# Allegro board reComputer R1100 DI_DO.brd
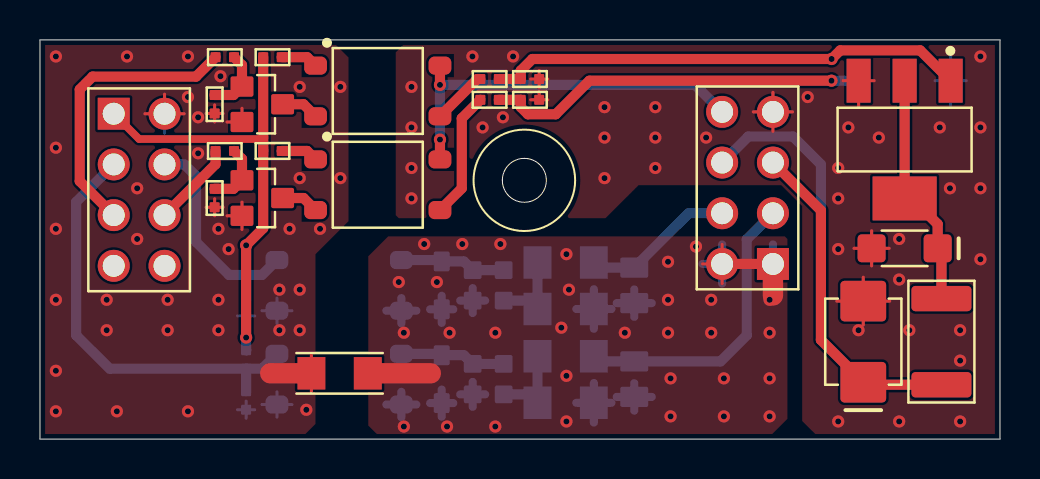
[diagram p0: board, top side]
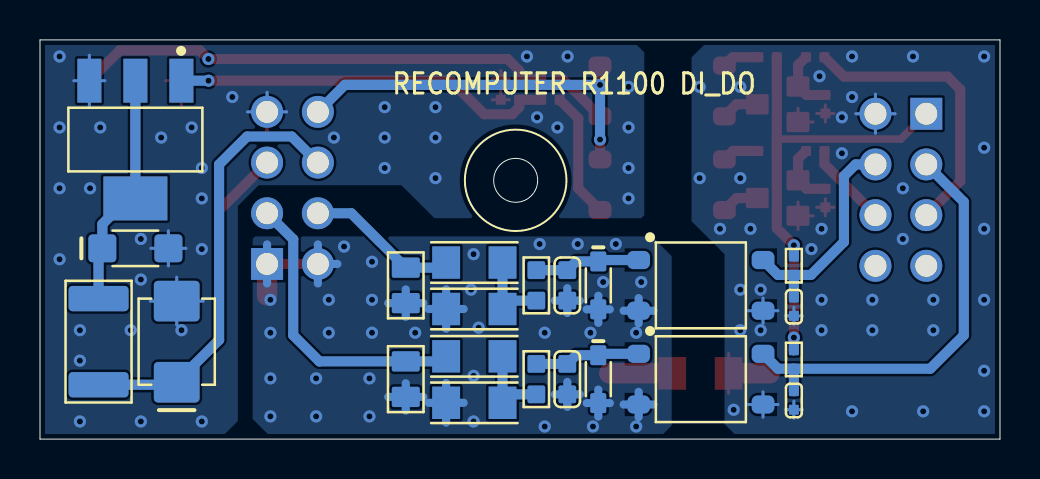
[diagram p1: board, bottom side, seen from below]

Outline 48 x 20 mm; copper layers: TOP, BOTTOM. Coordinates in mm from the lower left corner of the outline.
Outline path: circle c24.22,12.97 r1.1 ; 0,20 0,0 48,0 48,20 0,20

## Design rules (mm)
constraint set DEFAULT: min track width 0.152

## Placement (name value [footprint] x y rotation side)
C1  100nF  [C0603]  21.63 7.7 270 bottom
C2  10pF  [C0402]  10.31 6.63 270 bottom
C3  100nF  [C0603]  21.63 3 270 bottom
C4  10pF  [C0402]  10.31 1.94 270 bottom
D1  B5819WS SL  [SOD_323]  20.09 7.7 90 bottom
D2  B5819WS SL  [SOD_323]  20.09 3 90 bottom
D3  LMSZ5266BT1G  [SOD_123]  43.23 9.56 180 bottom
D4  SMBJ60CA/TR13  [DO_214AA_SMB]  41.16 4.88 270 bottom
D5  LMSZ5266BT1G  [SOD_123]  43.23 9.56 180 top
D6  SMBJ60CA/TR13  [DO_214AA_SMB]  41.16 4.88 270 top
F1  0.5A  [F1812]  45.07 4.88 270 bottom
F2  0.5A  [F1812]  45.07 4.88 270 top
J1  ST-PH-0096-2X4P-H2.0-PA3.0  [HEADER2X4P_2D54_DIP]  4.96 12.49 0 top
J2  ST-PH-0096-2X4P-H2.0-PA3.0  [HEADER2X4P_2D54_DIP]  35.38 12.58 180 top
Q1  SFH690BT3  [SOP4-2_54MM]  14.96 7.7 270 bottom
Q2  SFH690BT3  [SOP4-2_54MM]  14.96 3 270 bottom
Q3  SFH690BT3  [SOP4-2_54MM]  16.89 12.74 270 top
Q4  BCP56  [SOT223_4]  43.23 15.01 270 bottom
Q5  BSS138  [SOT23]  11.12 12.08 180 top
Q6  SFH690BT3  [SOP4-2_54MM]  16.89 17.44 270 top
Q7  BCP56  [SOT223_4]  43.23 15.01 270 top
Q8  BSS138  [SOT23]  11.12 16.78 180 top
R1  1M  [R1206]  14.98 3.3 180 top
R2  10K  [R0402]  10.31 8.69 270 bottom
R3  10K  [R0402]  10.31 3.99 270 bottom
R4  2.2K  [R1206]  26.28 8.85 180 bottom
R5  0R  [R0603]  23.18 7.7 90 bottom
R6  2.2K  [R1206]  26.28 4.15 180 bottom
R7  0R  [R0603]  23.18 3 90 bottom
R8  SDV2012A300C181NPTF  [R0805]  29.71 7.7 270 bottom
R9  2.2K  [R1206]  26.28 6.52 0 bottom
R10  2.2K  [R1206]  26.28 1.82 0 bottom
R11  SDV2012A300C181NPTF  [R0805]  29.71 3 270 bottom
R12  120R  [R0402]  11.62 14.44 0 top
R13  330R  [R0402]  22.48 17 0 top
R14  10K  [R0402]  24.5 17 0 top
R15  0R  [R0402]  9.24 14.44 0 top
R16  10K  [R0402]  8.73 12.08 270 top
R17  120R  [R0402]  11.62 19.14 0 top
R18  330R  [R0402]  22.48 18.04 0 top
R19  10K  [R0402]  24.5 18.04 0 top
R20  0R  [R0402]  9.24 19.14 0 top
R21  10K  [R0402]  8.73 16.78 270 top

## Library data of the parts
C1-C4 = CC
D1 D2 = D
D3 D5 = DIODE TVS
D4 D6 = DIODE TVS BI-DIR
F1 F2 = Fuse
J1 J2 = Header 2X4
Q1-Q3 Q6 = Optoisolator_4P
Q4 Q7 = NPN_4P
Q5 Q8 = NMOS_123
R1-R7 R9 R10 R12-R21 = R
R8 R11 = VDR

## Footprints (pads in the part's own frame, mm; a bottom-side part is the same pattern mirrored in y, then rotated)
C0402
  rrect 0.5x0.5 smd: 1(-0.463,0) 2(0.463,0)
C0603
  rrect 0.889x0.889 smd: 1(-0.762,0) 2(0.762,0)
DO_214AA_SMB
  rrect 2.032x2.286 smd: 1(-2.032,0) 2(2.032,0)
F1812
  rrect 1.27x3 smd: 1(-2.159,0) 2(2.159,0)
HEADER2X4P_2D54_DIP
  rect 1.6x1.6 hole 1.1: 1(-1.27,3.81)
  round 1.6 hole 1.1: 2(1.27,3.81) 3(-1.27,1.27) 4(1.27,1.27) 5(-1.27,-1.27) 6(1.27,-1.27) 7(-1.27,-3.81) 8(1.27,-3.81)
R0402
  rrect 0.5x0.5 smd: 1(-0.463,0) 2(0.463,0)
R0603
  rrect 0.889x0.889 smd: 1(-0.762,0) 2(0.762,0)
R0805
  rrect 1.016x1.397 smd: 1(-0.889,0) 2(0.889,0)
R1206
  rect 1.397x1.626 smd: 1(-1.41,0) 2(1.41,0)
SOD_123
  rrect 1.397x1.397 smd: 1(1.651,0) 2(-1.651,0)
SOD_323
  rrect 1x0.8 smd: 1(-1.2,0) 2(1.2,0)
SOP4-2_54MM
  rrect 0.91x1.14 smd: 1(-1.27,-3.11) 2(1.27,-3.11) 3(1.27,3.11) 4(-1.27,3.11)
SOT23
  rrect 1.143x1.016 smd: 1(1.016,-0.889) 2(1.016,0.889) 3(-1.016,0)
SOT223_4
  rect 2.2x1.2 smd: 1(-2.95,2.3) 2(-2.95,0) 3(-2.95,-2.3)
  rect 2.2x3.2 smd: 4(2.95,0)

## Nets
GND: C2.2 C4.2 J1.2 Q1.3(EMITTER) Q2.3(EMITTER) Q5.2(S) Q8.2(S) R1.2 R16.2 R21.2
GND_DO: D3.1 D4.1 D5.1 D6.1 J2.7 Q4.3(EMITTER) Q7.3(EMITTER) R14.2 R19.2
GND_ISO_DI: C1.2 C3.2 D1.1 D2.1 J2.1 J2.2 Q1.2 Q2.2 R1.1 R8.2 R9.2 R10.2 R11.2
VDD_3.3V: J1.1 R2.1 R3.1 R12.1 R17.1
CM4_IN1: C2.1 J1.4 Q1.4 R2.2
CM4_IN2: C4.1 J1.3 Q2.4 R3.2
CM4_OUTPUT1: J1.6 R15.1
CM4_OUTPUT2: J1.5 R20.1
DO_VDD: J2.8 Q3.4 Q6.4
EXT_IN1: J2.4 R4.1 R8.1
EXT_IN2: J2.3 R6.1 R11.1
EXT_OUT1: D4.2 F1.2 J2.6
EXT_OUT2: D6.2 F2.2 J2.5
N12939: R4.2 R5.1 R9.1
N12951: C1.1 D1.2(C) Q1.1 R5.2
N12997: R6.2 R7.1 R10.1
N13009: C3.1 D2.2(C) Q2.1 R7.2
N14695: D3.2(C) F1.1 Q4.2 Q4.4
N14789: Q3.1 R12.2
N14847: Q3.2 Q5.3
N14855: Q3.3(EMITTER) R13.1
N14859: Q4.1 R13.2 R14.1
N15023: Q5.1 R15.2 R16.1
N15163: D5.2(C) F2.1 Q7.2 Q7.4
N15257: Q6.1 R17.2
N15315: Q6.2 Q8.3
N15323: Q6.3(EMITTER) R18.1
N15327: Q7.1 R18.2 R19.1
N15491: Q8.1 R20.2 R21.1

Pads without a net: J1 7 8

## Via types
v1: diameter 0.61, hole 0.305, TOP to BOTTOM, 108 vias

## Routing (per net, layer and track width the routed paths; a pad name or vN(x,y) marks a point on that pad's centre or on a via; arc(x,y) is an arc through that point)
GND: length 26.8
  TOP w0.152: 8.3,11.62 R16.2 ; R16.2 8.73,12.04 ; R16.2 9.16,11.62 ; R16.2 8.73,11.19 ; 10.1,10.5 Q5.2 ; Q5.2 9.35,11.19 ; Q5.2 10.1,11.88 ; 8.73,15.89 R21.2 ; R21.2 8.3,16.31 ; R21.2 8.73,16.74 ; R21.2 9.16,16.31 ; J1.2 6.23,17.28 ; J1.2 7.21,16.3 ; J1.2 5.25,16.3 ; 9.35,15.89 Q8.2 10.1,16.57 ; 13.57,4.29 R1.2 13.57,2.31
  TOP w1.016: R1.2 11.51,3.3
  BOTTOM w0.152: C2.2 10.31,6.6 ; C2.2 10.74,6.17 ; C2.2 10.31,5.74 ; C2.2 9.88,6.17 ; Q1.3 12.6,6.43 ; Q1.3 11.85,7.07 ; Q1.3 11.1,6.43 ; Q1.3 11.85,5.8 ; C4.2 10.74,1.47 ; C4.2 9.88,1.47 ; C4.2 10.31,1.9 ; C4.2 10.31,1.04 ; J1.2 7.21,16.3 ; J1.2 6.23,15.32 ; J1.2 5.25,16.3 ; J1.2 6.23,17.28 ; Q2.3 11.85,2.37 ; Q2.3 11.1,1.73 ; Q2.3 12.6,1.73 ; Q2.3 11.85,1.1
  vias: v1(0.79,19.17) v1(0.79,14.6) v1(0.79,10.54) v1(0.79,6.98) v1(0.79,3.42) v1(0.79,1.39) v1(3.33,6.98) v1(3.33,5.46) v1(3.84,1.39) v1(4.35,19.17) v1(4.86,12.57) v1(4.86,10.03) v1(6.38,6.98) v1(6.38,5.46) v1(7.4,19.17) v1(7.4,17.14) v1(7.4,1.39) v1(7.91,16.12) v1(7.91,14.32) v1(8.92,10.54) v1(8.92,6.98) v1(8.92,5.46) v1(9.02,18.18) v1(9.43,9.52) v1(11.97,7.49) v1(11.97,5.46) v1(12.48,10.54) v1(12.99,17.65) v1(12.99,13.08) v1(12.99,7.49) v1(12.99,5.46) v1(13.32,1.47) v1(14,10.54) v1(15.02,17.65) v1(15.02,13.08)
GND_DO: length 33.9
  TOP w0.152: D6.1 42.49,6.91 ; D6.1 39.84,6.91 ; D6.1 41.16,8.11 ; D6.1 41.16,5.72 ; Q7.3 41.71,17.96 ; Q7.3 40.93,16.68 ; Q7.3 40.15,17.96 ; R14.2 25.39,17 ; R14.2 24.96,17.43 ; R14.2 24.53,17 ; D5.1 41.58,10.43 ; D5.1 42.46,9.56 ; D5.1 40.7,9.56 ; D5.1 41.58,8.68 ; J2.7 37.63,16.39 ; J2.7 36.65,15.42 ; J2.7 36.65,17.37 ; J2.7 35.67,16.39 ; 24.96,17.61 R19.2 ; R19.2 24.53,18.04 ; R19.2 24.96,18.47 ; R19.2 25.39,18.04
  BOTTOM w0.152: D6.1 41.16,8.11 ; D6.1 41.16,5.72 ; D6.1 42.49,6.91 ; D6.1 39.84,6.91 ; 40.7,9.56 D5.1 ; D5.1 42.46,9.56 ; D5.1 41.58,10.43 ; D5.1 41.58,8.68 ; Q4.3 45.53,19.24 ; Q4.3 45.53,16.68 ; Q4.3 46.31,17.96 ; Q4.3 44.75,17.96 ; J2.7 36.65,17.37 ; J2.7 37.63,16.39 ; J2.7 35.67,16.39
  vias: v1(18.57,17.65) v1(18.57,15.62) v1(18.57,13.58) v1(18.57,12.06) v1(21.62,19.17) v1(22.13,15.62) v1(23.15,16.12) v1(23.65,19.17) v1(28.23,16.63) v1(28.23,15.11) v1(28.23,13.08) v1(30.77,16.63) v1(30.77,15.11) v1(30.77,13.58) v1(33.31,15.11) v1(38.39,17.14) v1(39.91,13.58) v1(39.91,12.06) v1(39.91,9.52) v1(39.91,0.88) v1(40.42,15.62) v1(40.93,5.46) v1(41.94,15.11) v1(42.96,10.03) v1(42.96,8) v1(42.96,0.88) v1(43.47,5.46) v1(44.99,15.62) v1(45.5,12.57) v1(46.01,5.46) v1(46.01,3.93) v1(46.01,0.88) v1(47.02,19.17) v1(47.02,15.62) v1(47.02,12.57) v1(47.02,9.01)
GND_ISO_DI: length 44.4
  TOP w0.152: 33.13,8.77 J2.2 ; J2.2 34.11,7.8 ; J2.2 34.11,9.75
  TOP w0.508: J2.1 J2.2
  TOP w1.016: J2.1 36.65,7.19 ; R1.1 19.54,3.3
  BOTTOM w0.406: 26.82,6.52 R9.2 ; R9.2 28.57,6.52 ; R9.2 27.69,7.51 ; R9.2 27.69,5.53 ; 28.84,6.81 R8.2 ; R8.2 29.71,6.13 ; R8.2 29.71,7.5 ; R8.2 30.59,6.81 ; 33.13,8.77 J2.2 ; J2.2 34.11,9.75 ; J2.2 34.11,7.8 ; D1.1 20.66,6.5 ; D1.1 19.51,6.5 ; D1.1 20.09,7.18 ; D1.1 20.09,5.82 ; D2.1 20.66,1.8 ; D2.1 20.09,1.12 ; D2.1 19.51,1.8 ; D2.1 20.09,2.48 ; 27.69,0.83 R10.2 ; R10.2 28.57,1.82 ; R10.2 27.69,2.81 ; R10.2 26.82,1.82 ; 28.84,2.11 R11.2 ; R11.2 29.71,1.43 ; R11.2 30.59,2.11 ; R11.2 29.71,2.8 ; 36.65,9.75 J2.1 36.65,7.8 ; C1.2 21.63,7.56 ; C1.2 22.26,6.94 ; C1.2 21.01,6.94 ; C1.2 21.63,6.32 ; Q1.2 18.07,7.07 ; Q1.2 18.82,6.43 ; Q1.2 18.07,5.8 ; Q1.2 17.32,6.43 ; Q2.2 18.82,1.73 ; Q2.2 17.32,1.73 ; Q2.2 18.07,2.37 ; Q2.2 18.07,1.1 ; C3.2 22.26,2.24 ; C3.2 21.01,2.24 ; C3.2 21.63,1.62 ; C3.2 21.63,2.86
  vias: v1(17.94,7.87) v1(18.19,5.33) v1(18.19,0.63) v1(19.21,9.77) v1(19.84,7.87) v1(20.35,0.63) v1(20.48,5.33) v1(21.11,9.77) v1(22.77,5.33) v1(22.77,0.63) v1(23.02,9.77) v1(26.07,5.58) v1(26.32,9.27) v1(26.32,3.17) v1(26.32,0.88) v1(26.45,7.49) v1(29.24,5.33) v1(31.4,8.88) v1(31.4,6.98) v1(31.4,5.33) v1(31.53,3.04) v1(31.53,1.14) v1(32.8,9.65) v1(33.56,6.98) v1(33.56,5.33) v1(34.2,3.04) v1(34.2,1.14) v1(36.48,6.98) v1(36.48,5.33) v1(36.48,3.04) v1(36.48,1.14)
VDD_3.3V: length 23.6
  TOP w0.381: 11.16,15.11 11.09,15.03 4.96,15.03 J1.1
  TOP w0.508: v1(10.31,5.09) v1(10.31,9.71) 11.16,10.56 R12.1 R17.1
  BOTTOM w0.508: 10.31,4.45 R3.1 v1(10.31,5.09) ; R2.1 v1(10.31,9.71)
CM4_IN1: length 11.3
  BOTTOM w0.508: R2.2 C2.1 ; R2.2 9.45,8.23 7.8,9.87 7.8,13.18 7.22,13.76 J1.4 ; R2.2 11.1,8.23 Q1.4
CM4_IN2: length 21.5
  BOTTOM w0.508: Q2.4 11.1,3.53 R3.2 ; R3.2 3.49,3.53 1.81,5.2 1.81,11.88 J1.3 ; R3.2 C4.1
CM4_OUTPUT1: length 4.3
  TOP w0.508: J1.6 8.78,13.77 R15.1
CM4_OUTPUT2: length 14.5
  TOP w0.508: R20.1 7.8,18.16 2.63,18.16 1.99,17.52 1.99,12.92 J1.5
DO_VDD: length 19.4
  TOP w0.508: Q6.4 v1(20,17.75) ; Q3.4 v1(20,15.01)
  BOTTOM w0.508: J2.8 32.76,17.75 v1(20,17.75) v1(20,15.01)
EXT_IN1: length 7.6
  BOTTOM w0.508: R4.1 27.95,8.59 R8.1 32.44,11.31 J2.4
EXT_IN2: length 14.9
  BOTTOM w0.508: R6.1 27.95,3.89 R11.1 34.03,3.89 35.34,5.2 35.34,10.01 J2.3
EXT_OUT1: length 21.8
  BOTTOM w0.508: F1.2 41.29,2.72 D4.2 39.05,4.97 39.05,13.76 37.65,15.16 35.41,15.16 J2.6
EXT_OUT2: length 16.8
  TOP w0.508: F2.2 41.29,2.72 D6.2 39.05,4.97 39.05,11.46 J2.5
N12939: length 4.2
  BOTTOM w0.508: R4.2 R9.1 24.45,6.94 R5.1
N12951: length 5.3
  BOTTOM w0.508: Q1.1 20.02,8.97 D1.2 21.2,8.9 C1.1 R5.2
N12997: length 4.2
  BOTTOM w0.508: R7.1 24.45,2.24 R10.1 R6.2
N13009: length 5.3
  BOTTOM w0.508: Q2.1 20.02,4.27 D2.2 21.2,4.2 C3.1 R7.2
N14695: length 11.9
  BOTTOM w0.508: Q4.2 Q4.4 43.6,12.06 44.88,10.77 D3.2 45.07,9.37 F1.1
N14789: length 1.9
  TOP w0.508: Q3.1 13.36,14.44 R12.2
N14847: length 1.9
  TOP w0.508: Q5.3 13.18,12.08 Q3.2
N14855: length 6.4
  TOP w0.508: Q3.3 21.09,12.56 21.09,16.07 R13.1
N14859: length 19.2
  TOP w0.508: v1(39.58,17.96) 27.47,17.96 25.79,16.28 24.39,16.28 24.04,16.63 R14.1 R13.2
  BOTTOM w0.508: Q4.1 v1(39.58,17.96)
N15023: length 3.2
  TOP w0.508: R16.1 9.67,12.54 Q5.1 10.1,14.04 R15.2
N15163: length 11.9
  TOP w0.508: Q7.2 Q7.4 43.6,12.06 44.88,10.77 D5.2 45.07,9.37 F2.1
N15257: length 1.9
  TOP w0.508: Q6.1 13.36,19.14 R17.2
N15315: length 1.9
  TOP w0.508: Q6.2 13.18,16.78 Q8.3
N15323: length 2.8
  TOP w0.508: Q6.3 21.87,18.04 R18.1
N15327: length 24.1
  TOP w0.508: Q7.1 44.01,19.48 40.01,19.48 v1(39.58,19.04) 24.62,19.04 24.04,18.46 R19.1 R18.2
N15491: length 3.2
  TOP w0.508: R20.2 10.1,18.74 Q8.1 9.67,17.24 R21.1

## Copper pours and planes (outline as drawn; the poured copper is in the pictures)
GND on TOP: 0.25,19.75 14.8,19.75 15.42,19.12 15.42,10.92 13.77,9.27 13.77,0.76 13.27,0.25 0.25,0.25 ; 2 cut-outs
GND on BOTTOM: 0.25,19.75 14.8,19.75 15.42,19.12 15.42,10.92 13.77,9.27 13.77,0.76 13.27,0.25 0.25,0.25
GND_DO on TOP: 18.16,19.75 47.75,19.75 47.75,0.25 38.76,0.25 38.11,0.91 38.11,11.68 37.07,12.72 29.93,12.72 28.28,11.07 22.16,11.07 21.75,11.66 21.5,12.33 21.46,12.37 21.4,12.35 21.38,12.32 21.36,12.29 20.7,11.63 20.7,11.07 17.94,11.07 17.79,11.22 17.79,19.37
GND_DO on BOTTOM: 18.16,19.75 47.75,19.75 47.75,0.25 38.76,0.25 38.11,0.91 38.11,11.68 37.07,12.72 29.93,12.72 28.28,11.07 17.94,11.07 17.79,11.22 17.79,19.37
GND_ISO_DI on TOP: 37.24,10.15 37.37,10.03 37.37,1.01 36.61,0.25 16.84,0.25 16.42,0.68 16.42,9.16 17.41,10.15
GND_ISO_DI on BOTTOM: 37.24,10.15 37.37,10.03 37.37,1.01 36.61,0.25 16.84,0.25 16.42,0.68 16.42,9.16 17.41,10.15

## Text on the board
Ref Des/Silkscreen Bottom: RECOMPUTER R1100 DI_DO
PAGE_OUTLINE: HALF+PLATING | LAYER 1 - PRIMARY SIDE - SIGNAL | LAYER 2 - SECONDARY SIDE - SIGNAL | 50ohm SINGLE ENDED | IMPEDANCE CONTROL | +/- 10% | Clearance from Cu 5mil | 7.19/4.5 | 4.63/4.5 | COPPER WEIGHT | (OZ) | 1oz | TRACE WIDTH | (mil) | 90ohm DIFFERENTIAL | TRACE WIDTH/SPACE | 100ohm DIFFERENTIAL | 2 LAYER#---1.6MM | LAYER# | LAYER STACK-UP - ALL DIMENSIONS IN INCHES
User.23: FIGURE | FINISHED_SIZE | 12.0 | 43.31 | DRILL CHART: TOP to BOTTOM | ALL UNITS ARE IN MILS | PLATED | QTY | 108 | 16 | 124 | TOTAL HOLES:
